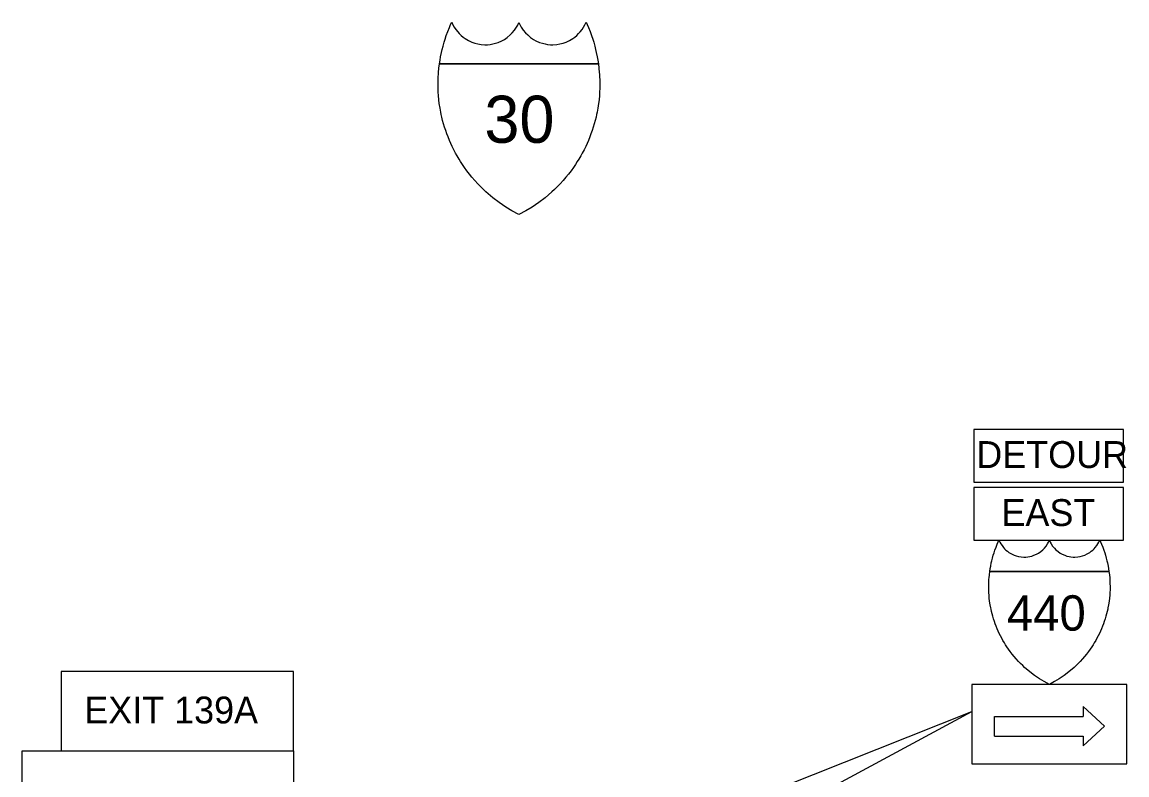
# Model space of a CAD drawing. Extents: x 755707 to 910811, y 936517 to 1037316.
# Drawn here: x 801641 to 834532, y 1004886 to 1027291 of the extents above; entities that cross this region are included whole.
import ezdxf

# ---------------------------------------------------------------- set-up
doc = ezdxf.new("R2010")
doc.units = 0
for name, color, linetype in [('23', 7, 'Continuous'), ('G-ANNO-TEXT', 7, 'Continuous'), ('Level 3', 7, 'Continuous'), ('Level 8', 7, 'Continuous'), ('R_Draft', 7, 'Continuous')]:
    doc.layers.add(name, color=color, linetype=linetype)

msp = doc.modelspace()

# ---------------------------------------------------------------- linework, layer by layer
at = {"layer": '23'}
for points in [[(814067, 1026047), (814084, 1026160), (814102, 1026260), (814128, 1026389), (814148, 1026473), (814173, 1026573), (814206, 1026690), (814236, 1026788), (814270, 1026889), (814315, 1027013), (814362, 1027130), (814400, 1027220), (814432, 1027291), (814467, 1027215), (814508, 1027141), (814552, 1027074), (814609, 1027000), (814655, 1026949), (814711, 1026895), (814768, 1026847), (814830, 1026802), (814928, 1026744), (815029, 1026697), (815120, 1026664), (815210, 1026641), (815306, 1026625), (815419, 1026618), (815492, 1026619), (815577, 1026627), (815653, 1026640), (815733, 1026660), (815815, 1026687), (815924, 1026735), (816000, 1026777), (816087, 1026837), (816172, 1026908), (816233, 1026970), (816303, 1027055), (816361, 1027142), (816395, 1027203), (816432, 1027283)], [(816432, 1027283), (816469, 1027203), (816503, 1027142), (816561, 1027055), (816631, 1026970), (816693, 1026908), (816777, 1026837), (816865, 1026777), (816940, 1026735), (817049, 1026687), (817131, 1026660), (817212, 1026640), (817287, 1026627), (817372, 1026619), (817446, 1026618), (817558, 1026625), (817655, 1026641), (817745, 1026664), (817836, 1026697), (817937, 1026744), (818035, 1026802), (818096, 1026847), (818153, 1026895), (818210, 1026949), (818255, 1027000), (818313, 1027074), (818357, 1027141), (818397, 1027215), (818432, 1027291), (818464, 1027220), (818503, 1027130), (818549, 1027013), (818594, 1026889), (818628, 1026788), (818658, 1026690), (818691, 1026573), (818717, 1026473), (818736, 1026389), (818763, 1026260), (818780, 1026160), (818798, 1026047)], [(816432, 1021566), (816225, 1021676), (816043, 1021786), (815842, 1021922), (815655, 1022063), (815450, 1022238), (815373, 1022309), (815287, 1022394), (815206, 1022477), (815118, 1022574), (815031, 1022674), (814959, 1022763), (814881, 1022865), (814810, 1022964), (814748, 1023054), (814694, 1023138), (814649, 1023210), (814590, 1023311), (814544, 1023394), (814493, 1023490), (814444, 1023590), (814401, 1023683), (814363, 1023772), (814322, 1023872), (814286, 1023965), (814252, 1024062), (814219, 1024163), (814188, 1024267), (814161, 1024366), (814137, 1024460), (814118, 1024544), (814105, 1024606), (814083, 1024726), (814061, 1024865), (814046, 1024981), (814036, 1025103), (814030, 1025202), (814025, 1025328), (814024, 1025445), (814026, 1025575), (814030, 1025660), (814034, 1025739), (814038, 1025788), (814050, 1025916), (814067, 1026047)], [(818798, 1026047), (814067, 1026047)], [(814067, 1026047), (818798, 1026047)], [(818798, 1026047), (818814, 1025916), (818826, 1025788), (818830, 1025739), (818835, 1025660), (818838, 1025575), (818841, 1025445), (818839, 1025328), (818835, 1025202), (818829, 1025103), (818818, 1024981), (818803, 1024865), (818782, 1024726), (818759, 1024606), (818746, 1024544), (818727, 1024460), (818704, 1024366), (818676, 1024267), (818645, 1024163), (818612, 1024062), (818578, 1023965), (818543, 1023872), (818502, 1023772), (818463, 1023683), (818420, 1023590), (818371, 1023490), (818320, 1023394), (818274, 1023311), (818215, 1023210), (818170, 1023138), (818116, 1023054), (818055, 1022964), (817983, 1022865), (817905, 1022763), (817833, 1022674), (817746, 1022574), (817658, 1022477), (817578, 1022394), (817491, 1022309), (817414, 1022238), (817210, 1022063), (817022, 1021922), (816822, 1021786), (816639, 1021676), (816432, 1021566)], [(830450, 1010942), (830463, 1011027), (830477, 1011102), (830496, 1011198), (830511, 1011261), (830530, 1011336), (830555, 1011424), (830577, 1011498), (830603, 1011573), (830637, 1011666), (830671, 1011754), (830700, 1011822), (830724, 1011875), (830751, 1011817), (830781, 1011762), (830814, 1011712), (830857, 1011656), (830891, 1011619), (830933, 1011578), (830976, 1011542), (831022, 1011508), (831096, 1011464), (831172, 1011429), (831240, 1011405), (831307, 1011387), (831380, 1011375), (831464, 1011370), (831520, 1011371), (831583, 1011377), (831640, 1011386), (831700, 1011401), (831761, 1011422), (831843, 1011458), (831900, 1011489), (831966, 1011534), (832029, 1011587), (832075, 1011634), (832127, 1011698), (832171, 1011763), (832196, 1011808), (832224, 1011868)], [(832224, 1011868), (832252, 1011808), (832278, 1011763), (832321, 1011698), (832374, 1011634), (832420, 1011587), (832483, 1011534), (832549, 1011489), (832605, 1011458), (832687, 1011422), (832748, 1011401), (832809, 1011386), (832866, 1011377), (832929, 1011371), (832985, 1011370), (833069, 1011375), (833141, 1011387), (833209, 1011405), (833277, 1011429), (833353, 1011464), (833426, 1011508), (833473, 1011542), (833515, 1011578), (833557, 1011619), (833591, 1011656), (833635, 1011712), (833668, 1011762), (833698, 1011817), (833724, 1011875), (833748, 1011822), (833777, 1011754), (833812, 1011666), (833846, 1011573), (833871, 1011498), (833894, 1011424), (833919, 1011336), (833938, 1011261), (833952, 1011198), (833972, 1011102), (833985, 1011027), (833998, 1010942)], [(832224, 1007581), (832069, 1007664), (831932, 1007746), (831782, 1007848), (831641, 1007954), (831488, 1008085), (831430, 1008138), (831365, 1008202), (831305, 1008264), (831239, 1008337), (831174, 1008412), (831120, 1008479), (831061, 1008555), (831008, 1008629), (830961, 1008697), (830921, 1008760), (830887, 1008814), (830843, 1008890), (830808, 1008952), (830770, 1009024), (830733, 1009099), (830701, 1009168), (830672, 1009235), (830641, 1009311), (830615, 1009380), (830589, 1009453), (830564, 1009529), (830541, 1009607), (830521, 1009681), (830503, 1009751), (830489, 1009814), (830479, 1009861), (830462, 1009951), (830446, 1010056), (830435, 1010142), (830427, 1010234), (830422, 1010308), (830419, 1010402), (830418, 1010490), (830420, 1010587), (830422, 1010652), (830426, 1010711), (830429, 1010748), (830438, 1010844), (830450, 1010942)], [(833998, 1010942), (830450, 1010942)], [(830450, 1010942), (833998, 1010942)], [(833998, 1010942), (834011, 1010844), (834020, 1010748), (834023, 1010711), (834026, 1010652), (834029, 1010587), (834031, 1010490), (834030, 1010402), (834026, 1010308), (834022, 1010234), (834014, 1010142), (834003, 1010056), (833986, 1009951), (833969, 1009861), (833960, 1009814), (833945, 1009751), (833928, 1009681), (833908, 1009607), (833884, 1009529), (833859, 1009453), (833834, 1009380), (833807, 1009311), (833777, 1009235), (833747, 1009168), (833715, 1009099), (833678, 1009024), (833640, 1008952), (833606, 1008890), (833561, 1008814), (833528, 1008760), (833487, 1008697), (833441, 1008629), (833388, 1008555), (833329, 1008479), (833275, 1008412), (833210, 1008337), (833144, 1008264), (833083, 1008202), (833018, 1008138), (832961, 1008085), (832807, 1007954), (832667, 1007848), (832517, 1007746), (832380, 1007664), (832224, 1007581)]]:
    msp.add_lwpolyline(points, dxfattribs=at)
at = {"layer": 'Level 3'}
msp.add_line((830595, 1006041), (830595, 1006628), dxfattribs=at)
at = {"layer": 'Level 8'}
for p, q in [((833228, 1006921), (833870, 1006335)), ((833228, 1006921), (833228, 1006628)), ((830595, 1006628), (833228, 1006628)), ((833870, 1006335), (833228, 1005748)), ((830595, 1006041), (833228, 1006041)), ((833228, 1006041), (833228, 1005748))]:
    msp.add_line(p, q, dxfattribs=at)
for points in [[(829980, 1013595), (834436, 1013595), (834436, 1015169), (829980, 1015169)], [(829980, 1011868), (834436, 1011868), (834436, 1013442), (829980, 1013442)], [(809721, 1007965), (802801, 1007965), (802801, 1005604), (809721, 1005604)], [(829916, 1005220), (834532, 1005220), (834532, 1007581), (829916, 1007581)], [(809721, 1005604), (809721, 995421), (801641, 995421), (801641, 1005604)]]:
    msp.add_lwpolyline(points, close=True, dxfattribs=at)
at = {"layer": 'R_Draft'}
for p in [(818628, 1002293), (823457, 1003292)]:
    msp.add_line(p, (829916, 1006774), dxfattribs=at)

# ---------------------------------------------------------------- texts
at = {"layer": 'G-ANNO-TEXT'}
for s, height, p in [('30', 1402.1, (815404, 1023699)), ('440', 1051.6, (830961, 1009180))]:
    msp.add_text(s, height=height, dxfattribs=at).set_placement(p)
at = {"layer": 'R_Draft'}
for s, p in [('DETOUR', (830048, 1014020)), ('EAST', (830798, 1012293)), ('EXIT 139A', (803492, 1006417))]:
    msp.add_text(s, height=800, dxfattribs=at).set_placement(p)

doc.saveas('drawing.dxf')
